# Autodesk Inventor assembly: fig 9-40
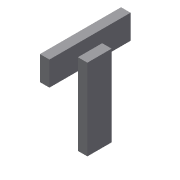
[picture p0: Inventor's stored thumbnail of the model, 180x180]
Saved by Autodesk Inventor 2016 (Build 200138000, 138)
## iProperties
Created: 2013-07
Part Number: fig 9-40
Document SubType Name: Assembly
Designer: CADCIM
Author: CADCIM
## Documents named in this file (2)
- D:\KAVITA\Autodesk Inventor_ 2016 Project_Kavita\Inventor_Part Files\Inventor_2016_Part\c09_Inv_2016\c09_inv_2016_prt\fig 9-40.iam
- D:\KAVITA\Autodesk Inventor_ 2016 Project_Kavita\Inventor_Part Files\Inventor_2016_Part\c09_Inv_2016\c09_inv_2016_prt\12.ipt
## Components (2 placed, 1 different names)
1. 12:1 — Rigid:1
2. 12:2 — Rigid:1
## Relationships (1: WeldJoint 1)
- Rigid:1 [WeldJoint]: 12:1 ↔ 12:2
